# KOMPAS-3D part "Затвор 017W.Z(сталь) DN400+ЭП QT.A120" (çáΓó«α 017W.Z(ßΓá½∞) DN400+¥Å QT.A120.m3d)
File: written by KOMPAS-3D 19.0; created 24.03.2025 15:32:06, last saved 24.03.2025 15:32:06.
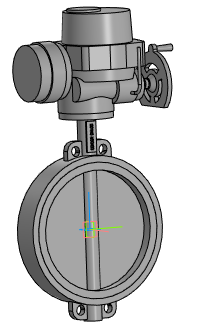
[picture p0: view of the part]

Document properties: Полное имя файла: Затвор 017W.Z(сталь) DN400+ЭП QT.A120.a3d

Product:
- Part/product: Затвор 017W.Z(сталь) DN400+ЭП QT.A120
    Масса: 225.14

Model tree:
1. Операция без истории:1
